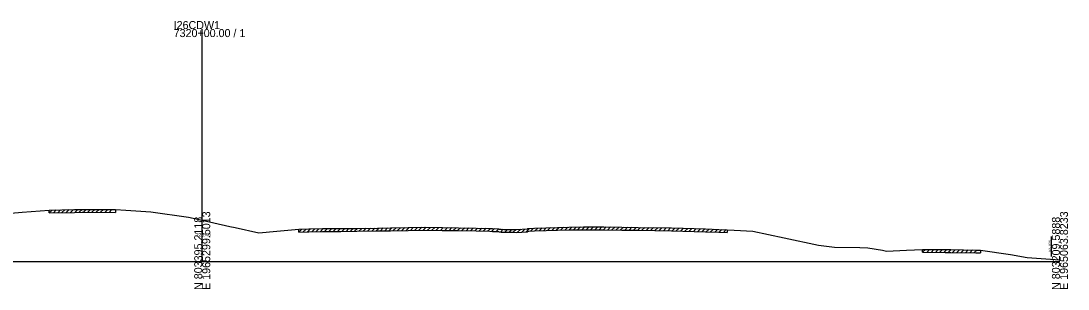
# Model space of a CAD drawing. Extents: x -26 to 1986619, y -10 to 827846.
# Drawn here: x 236.6 to 602.8, y 990.3 to 1084.1 of the extents above; entities that cross this region are included whole.
import ezdxf

# ---------------------------------------------------------------- set-up
doc = ezdxf.new("R2010")
doc.units = 0
for name, color, linetype in [('RD_GPK_XS_Cell', 7, 'Continuous'), ('RD_XS_ExGround', 7, 'Continuous'), ('RD_XS_ExPaveRet', 7, 'Continuous'), ('RD_XS_ExRW', 7, 'Continuous'), ('RD_XS_TX_Elev_EX', 7, 'Continuous')]:
    doc.layers.add(name, color=color, linetype=linetype)

msp = doc.modelspace()

# ---------------------------------------------------------------- linework, layer by layer
at = {"layer": 'RD_GPK_XS_Cell'}
for p, q in [((300, 1000), (300, 1081.27)), ((0, 1000), (300, 1000)), ((300, 1000), (600, 1000))]:
    msp.add_line(p, q, dxfattribs=at)
at = {"layer": 'RD_XS_ExGround'}
msp.add_lwpolyline([(228.99, 1016.54), (237.03, 1017.2), (246.44, 1017.93), (255.33, 1018.15), (258.01, 1018.2), (258.73, 1018.2), (269.64, 1018.12), (273.28, 1017.9), (282.01, 1017.38), (295.24, 1015.41), (295.78, 1015.33), (296.2, 1015.24), (300, 1014.4), (309.7, 1012.25), (311.56, 1011.83), (319.85, 1009.97), (326.05, 1010.52), (333.81, 1011.27), (337.23, 1011.34), (342.1, 1011.45), (348.49, 1011.48), (354.06, 1011.53), (361.34, 1011.64), (365.88, 1011.72), (372, 1011.82), (377.72, 1011.92), (383.91, 1011.84), (389.69, 1011.77), (395.81, 1011.65), (400.61, 1011.55), (401.54, 1011.5), (403.59, 1011.4), (403.85, 1011.28), (404.52, 1011.24), (405.51, 1011.19), (406.31, 1011.2), (407.09, 1011.19), (408.7, 1011.17), (409.93, 1011.14), (413.72, 1011.38), (413.87, 1011.48), (414.23, 1011.51), (416.2, 1011.64), (420.35, 1011.76), (428.25, 1012), (433.37, 1012.04), (440.44, 1012.08), (446.72, 1011.97), (452.5, 1011.88), (464.12, 1011.68), (476.07, 1011.35), (480.67, 1011.18), (483.56, 1011.08), (486.06, 1010.93), (492.64, 1010.6), (503.6, 1008.21), (515.5, 1005.64), (521.15, 1004.93), (529.97, 1004.82), (532.84, 1004.75), (537.89, 1003.88), (539.38, 1003.52), (546.37, 1003.9), (551.93, 1004.16), (559.89, 1004.11), (561.86, 1004.11), (570.59, 1003.97), (572.19, 1003.95), (582.72, 1002.42), (588.59, 1001.34), (600, 1000.55)], dxfattribs=at)
at = {"layer": 'RD_XS_ExPaveRet'}
for p, q in [((256.94, 1017.18), (257.96, 1018.2)), ((258.44, 1017.2), (259.43, 1018.19)), ((246.44, 1016.93), (247.46, 1017.95)), ((246.44, 1016.93), (246.44, 1017.93)), ((246.44, 1016.93), (255.33, 1017.15)), ((247.94, 1016.96), (248.96, 1017.99)), ((249.44, 1017), (250.46, 1018.03)), ((250.94, 1017.04), (251.96, 1018.07)), ((252.44, 1017.08), (253.46, 1018.1)), ((253.94, 1017.12), (254.96, 1018.14)), ((255.33, 1017.15), (258.01, 1017.2)), ((255.44, 1017.15), (256.46, 1018.17)), ((258.01, 1017.2), (258.73, 1017.2)), ((258.73, 1017.2), (269.64, 1017.12)), ((259.94, 1017.19), (260.93, 1018.18)), ((261.44, 1017.18), (262.43, 1018.17)), ((262.94, 1017.17), (263.93, 1018.16)), ((264.44, 1017.16), (265.43, 1018.15)), ((265.94, 1017.15), (266.93, 1018.14)), ((267.44, 1017.13), (268.43, 1018.13)), ((269.64, 1018.12), (269.64, 1017.12)), ((333.81, 1010.27), (334.84, 1011.29)), ((333.81, 1010.27), (333.81, 1011.27)), ((335.31, 1010.3), (336.34, 1011.32)), ((336.81, 1010.33), (337.83, 1011.36)), ((338.31, 1010.37), (339.33, 1011.39)), ((339.81, 1010.4), (340.83, 1011.42)), ((341.31, 1010.43), (342.33, 1011.45)), ((342.81, 1010.45), (343.82, 1011.46)), ((344.31, 1010.46), (345.32, 1011.46)), ((345.81, 1010.47), (346.82, 1011.47)), ((347.31, 1010.48), (348.32, 1011.48)), ((348.81, 1010.49), (349.82, 1011.49)), ((350.31, 1010.5), (351.32, 1011.5)), ((351.81, 1010.51), (352.82, 1011.52)), ((353.31, 1010.52), (354.32, 1011.53)), ((354.81, 1010.54), (355.83, 1011.55)), ((356.31, 1010.56), (357.33, 1011.58)), ((357.81, 1010.59), (358.83, 1011.6)), ((359.31, 1010.61), (360.33, 1011.63)), ((360.81, 1010.64), (361.83, 1011.65)), ((362.31, 1010.66), (363.33, 1011.68)), ((363.81, 1010.69), (364.83, 1011.7)), ((365.31, 1010.71), (366.33, 1011.73)), ((366.81, 1010.74), (367.83, 1011.75)), ((368.31, 1010.76), (369.33, 1011.78)), ((369.81, 1010.79), (370.83, 1011.8)), ((371.31, 1010.81), (372.33, 1011.83)), ((372, 1010.82), (377.72, 1010.92)), ((372.81, 1010.84), (373.83, 1011.85)), ((374.31, 1010.86), (375.33, 1011.88)), ((375.81, 1010.89), (376.83, 1011.91)), ((377.31, 1010.91), (378.31, 1011.91)), ((377.72, 1010.92), (383.91, 1010.84)), ((378.81, 1010.91), (379.8, 1011.89)), ((380.31, 1010.89), (381.3, 1011.88)), ((381.81, 1010.87), (382.8, 1011.86)), ((383.31, 1010.85), (384.3, 1011.84)), ((384.81, 1010.83), (385.8, 1011.82)), ((386.31, 1010.81), (387.3, 1011.8)), ((387.81, 1010.79), (388.8, 1011.78)), ((389.31, 1010.78), (390.3, 1011.76)), ((390.81, 1010.75), (391.79, 1011.73)), ((392.31, 1010.72), (393.29, 1011.7)), ((393.81, 1010.69), (394.79, 1011.67)), ((395.31, 1010.66), (396.29, 1011.64)), ((396.81, 1010.63), (397.79, 1011.61)), ((398.31, 1010.6), (399.29, 1011.58)), ((399.81, 1010.57), (400.79, 1011.54)), ((401.31, 1010.51), (402.26, 1011.47)), ((402.81, 1010.44), (403.71, 1011.34)), ((404.31, 1010.25), (405.27, 1011.21)), ((405.81, 1010.2), (406.81, 1011.2)), ((407.31, 1010.19), (408.3, 1011.17)), ((408.81, 1010.16), (409.79, 1011.14)), ((410.31, 1010.16), (411.38, 1011.23)), ((411.81, 1010.26), (412.88, 1011.32)), ((413.31, 1010.35), (414.49, 1011.52)), ((414.81, 1010.55), (415.89, 1011.62)), ((416.31, 1010.64), (417.34, 1011.67)), ((417.81, 1010.69), (418.84, 1011.72)), ((419.31, 1010.73), (420.34, 1011.76)), ((420.35, 1010.76), (428.25, 1011)), ((420.81, 1010.78), (421.84, 1011.81)), ((422.31, 1010.82), (423.34, 1011.85)), ((423.81, 1010.86), (424.84, 1011.89)), ((425.31, 1010.91), (426.34, 1011.94)), ((426.81, 1010.95), (427.84, 1011.98)), ((428.25, 1011), (433.37, 1011.04)), ((428.31, 1011), (429.32, 1012)), ((429.81, 1011.01), (430.82, 1012.02)), ((431.31, 1011.02), (432.32, 1012.03)), ((432.81, 1011.03), (433.82, 1012.04)), ((433.37, 1011.04), (440.44, 1011.08)), ((434.31, 1011.04), (435.32, 1012.05)), ((435.81, 1011.05), (436.82, 1012.06)), ((437.31, 1011.06), (438.32, 1012.07)), ((438.81, 1011.07), (439.82, 1012.08)), ((440.31, 1011.08), (441.3, 1012.07)), ((440.44, 1011.08), (446.72, 1010.97)), ((441.81, 1011.06), (442.79, 1012.04)), ((443.31, 1011.03), (444.29, 1012.01)), ((444.81, 1011), (445.79, 1011.99)), ((446.31, 1010.98), (447.3, 1011.96)), ((446.72, 1010.97), (452.5, 1010.88)), ((447.81, 1010.95), (448.8, 1011.94)), ((449.31, 1010.93), (450.3, 1011.91)), ((450.81, 1010.91), (451.8, 1011.89)), ((452.31, 1010.88), (453.3, 1011.87)), ((452.5, 1010.88), (464.12, 1010.68)), ((453.81, 1010.86), (454.8, 1011.84)), ((455.31, 1010.83), (456.3, 1011.81)), ((456.81, 1010.81), (457.8, 1011.79)), ((458.31, 1010.78), (459.3, 1011.76)), ((459.81, 1010.75), (460.8, 1011.73)), ((461.31, 1010.73), (462.3, 1011.71)), ((462.81, 1010.7), (463.8, 1011.68)), ((464.31, 1010.67), (465.29, 1011.64)), ((465.81, 1010.63), (466.79, 1011.6)), ((467.31, 1010.59), (468.29, 1011.56)), ((468.81, 1010.55), (469.79, 1011.52)), ((470.31, 1010.51), (471.29, 1011.48)), ((471.81, 1010.47), (472.79, 1011.44)), ((473.31, 1010.43), (474.29, 1011.4)), ((474.81, 1010.39), (475.79, 1011.36)), ((476.31, 1010.34), (477.28, 1011.31)), ((477.81, 1010.29), (478.78, 1011.25)), ((479.31, 1010.23), (480.28, 1011.2)), ((480.81, 1010.18), (481.78, 1011.14)), ((482.31, 1010.13), (483.28, 1011.09)), ((483.56, 1011.08), (483.56, 1010.08)), ((333.81, 1010.27), (337.23, 1010.34)), ((337.23, 1010.34), (342.1, 1010.45)), ((342.1, 1010.45), (348.49, 1010.48)), ((348.49, 1010.48), (354.06, 1010.53)), ((354.06, 1010.53), (361.34, 1010.64)), ((361.34, 1010.64), (365.88, 1010.72)), ((365.88, 1010.72), (372, 1010.82)), ((383.91, 1010.84), (389.69, 1010.77)), ((389.69, 1010.77), (395.81, 1010.65)), ((395.81, 1010.65), (400.61, 1010.55)), ((400.61, 1010.55), (401.54, 1010.5)), ((401.54, 1010.5), (403.59, 1010.4)), ((403.59, 1010.4), (403.85, 1010.28)), ((403.85, 1010.28), (404.52, 1010.24)), ((404.52, 1010.24), (405.51, 1010.19)), ((405.51, 1010.19), (406.31, 1010.2)), ((406.31, 1010.2), (407.09, 1010.19)), ((407.09, 1010.19), (408.7, 1010.17)), ((408.7, 1010.17), (409.93, 1010.14)), ((409.93, 1010.14), (413.72, 1010.38)), ((413.72, 1010.38), (413.87, 1010.48)), ((413.87, 1010.48), (414.23, 1010.51)), ((414.23, 1010.51), (416.2, 1010.64)), ((416.2, 1010.64), (420.35, 1010.76)), ((464.12, 1010.68), (476.07, 1010.35)), ((476.07, 1010.35), (480.67, 1010.18)), ((480.67, 1010.18), (483.56, 1010.08)), ((551.93, 1003.16), (551.93, 1004.16)), ((551.93, 1003.16), (552.92, 1004.15)), ((553.43, 1003.15), (554.42, 1004.14)), ((554.93, 1003.14), (555.92, 1004.13)), ((556.43, 1003.13), (557.42, 1004.12)), ((557.93, 1003.12), (558.92, 1004.11)), ((559.43, 1003.11), (560.42, 1004.11)), ((560.93, 1003.11), (561.93, 1004.11)), ((562.43, 1003.1), (563.41, 1004.09)), ((563.93, 1003.08), (564.91, 1004.06)), ((565.43, 1003.05), (566.41, 1004.04)), ((566.93, 1003.03), (567.91, 1004.02)), ((568.43, 1003.01), (569.41, 1003.99)), ((569.93, 1002.98), (570.91, 1003.97)), ((572.19, 1003.95), (572.19, 1002.95)), ((551.93, 1003.16), (559.89, 1003.11)), ((559.89, 1003.11), (561.86, 1003.11)), ((561.86, 1003.11), (570.59, 1002.97)), ((570.59, 1002.97), (572.19, 1002.95))]:
    msp.add_line(p, q, dxfattribs=at)
at = {"layer": 'RD_XS_ExRW'}
msp.add_line((597, 1001.75), (597, 1008.75), dxfattribs=at)

# ---------------------------------------------------------------- texts
at = {"layer": 'RD_GPK_XS_Cell'}
for s, p in [('I26CDW1', (290, 1081.27)), ('7320+00.00 / 1', (290, 1078.47))]:
    msp.add_text(s, height=2.8, dxfattribs=at).set_placement(p)
for s, p in [('N 803395.2118', (300, 990)), ('E 1965299.5013', (302.8, 990)), ('N 803209.5888', (600, 990)), ('E 1965063.8233', (602.8, 990))]:
    msp.add_text(s, height=2.8, rotation=90, dxfattribs=at).set_placement(p)
at = {"layer": 'RD_XS_ExRW'}
msp.add_text('EX. R/W ', height=0.75, rotation=90, dxfattribs=at).set_placement((596.75, 1003.44))
at = {"layer": 'RD_XS_TX_Elev_EX'}
msp.add_text('223.40', height=1.2, dxfattribs=at).set_placement((297.85, 1008.7))

doc.saveas('drawing.dxf')
